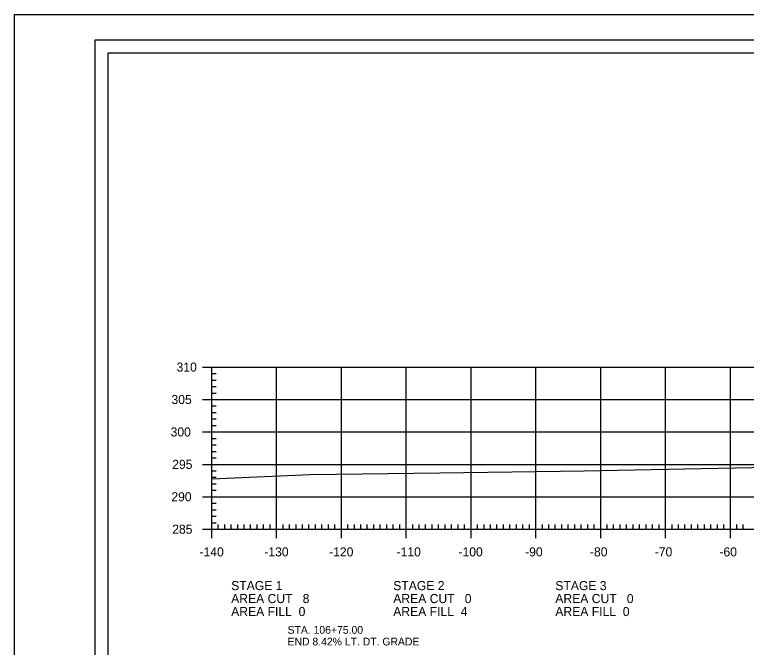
# Model space of a CAD drawing. Extents: x 1368713 to 1370673, y 380279 to 380950.
# Drawn here: x 1369981.9 to 1370094.8, y 380639.5 to 380737.1 of the extents above; entities that cross this region are included whole.
import ezdxf

# ---------------------------------------------------------------- set-up
doc = ezdxf.new("R2010")
doc.units = 0
for name, color, linetype in [('Notes', 7, 'Continuous'), ('R_Axis', 7, 'Continuous'), ('R_Axis Annot', 7, 'Continuous'), ('R_Border', 7, 'Continuous'), ('R_Exist Surface', 7, 'Continuous'), ('R_Grid', 7, 'Continuous'), ('R_No Plot', 7, 'Continuous')]:
    doc.layers.add(name, color=color, linetype=linetype)

msp = doc.modelspace()

# ---------------------------------------------------------------- linework, layer by layer
at = {"layer": 'R_Axis'}
for p, q in [((1370010.88, 380682.75), (1370013.68, 380682.75)), ((1370012.28, 380657.75), (1370012.28, 380682.75)), ((1370012.28, 380681.75), (1370012.98, 380681.75)), ((1370012.28, 380680.75), (1370012.98, 380680.75)), ((1370012.28, 380679.75), (1370012.98, 380679.75)), ((1370010.88, 380677.75), (1370013.68, 380677.75)), ((1370012.28, 380678.75), (1370012.98, 380678.75)), ((1370012.28, 380676.75), (1370012.98, 380676.75)), ((1370012.28, 380675.75), (1370012.98, 380675.75)), ((1370012.28, 380674.75), (1370012.98, 380674.75)), ((1370012.28, 380673.75), (1370012.98, 380673.75)), ((1370010.88, 380672.75), (1370013.68, 380672.75)), ((1370012.28, 380671.75), (1370012.98, 380671.75)), ((1370012.28, 380670.75), (1370012.98, 380670.75)), ((1370012.28, 380669.75), (1370012.98, 380669.75)), ((1370012.28, 380668.75), (1370012.98, 380668.75)), ((1370010.88, 380667.75), (1370013.68, 380667.75)), ((1370012.28, 380666.75), (1370012.98, 380666.75)), ((1370012.28, 380665.75), (1370012.98, 380665.75)), ((1370012.28, 380664.75), (1370012.98, 380664.75)), ((1370012.28, 380663.75), (1370012.98, 380663.75)), ((1370010.88, 380662.75), (1370013.68, 380662.75)), ((1370012.28, 380661.75), (1370012.98, 380661.75)), ((1370012.28, 380660.75), (1370012.98, 380660.75)), ((1370012.28, 380659.75), (1370012.98, 380659.75)), ((1370012.28, 380656.35), (1370012.28, 380659.15)), ((1370012.28, 380658.75), (1370012.98, 380658.75)), ((1370022.28, 380656.35), (1370022.28, 380659.15)), ((1370032.28, 380656.35), (1370032.28, 380659.15)), ((1370042.28, 380656.35), (1370042.28, 380659.15)), ((1370052.28, 380656.35), (1370052.28, 380659.15)), ((1370062.28, 380656.35), (1370062.28, 380659.15)), ((1370072.28, 380656.35), (1370072.28, 380659.15)), ((1370082.28, 380656.35), (1370082.28, 380659.15)), ((1370092.28, 380656.35), (1370092.28, 380659.15)), ((1370010.88, 380657.75), (1370013.68, 380657.75)), ((1370012.28, 380657.75), (1370292.28, 380657.75)), ((1370013.28, 380657.75), (1370013.28, 380658.45)), ((1370014.28, 380657.75), (1370014.28, 380658.45)), ((1370015.28, 380657.75), (1370015.28, 380658.45)), ((1370016.28, 380657.75), (1370016.28, 380658.45)), ((1370017.28, 380657.75), (1370017.28, 380658.45)), ((1370018.28, 380657.75), (1370018.28, 380658.45)), ((1370019.28, 380657.75), (1370019.28, 380658.45)), ((1370020.28, 380657.75), (1370020.28, 380658.45)), ((1370021.28, 380657.75), (1370021.28, 380658.45)), ((1370023.28, 380657.75), (1370023.28, 380658.45)), ((1370024.28, 380657.75), (1370024.28, 380658.45)), ((1370025.28, 380657.75), (1370025.28, 380658.45)), ((1370026.28, 380657.75), (1370026.28, 380658.45)), ((1370027.28, 380657.75), (1370027.28, 380658.45)), ((1370028.28, 380657.75), (1370028.28, 380658.45)), ((1370029.28, 380657.75), (1370029.28, 380658.45)), ((1370030.28, 380657.75), (1370030.28, 380658.45)), ((1370031.28, 380657.75), (1370031.28, 380658.45)), ((1370033.28, 380657.75), (1370033.28, 380658.45)), ((1370034.28, 380657.75), (1370034.28, 380658.45)), ((1370035.28, 380657.75), (1370035.28, 380658.45)), ((1370036.28, 380657.75), (1370036.28, 380658.45)), ((1370037.28, 380657.75), (1370037.28, 380658.45)), ((1370038.28, 380657.75), (1370038.28, 380658.45)), ((1370039.28, 380657.75), (1370039.28, 380658.45)), ((1370040.28, 380657.75), (1370040.28, 380658.45)), ((1370041.28, 380657.75), (1370041.28, 380658.45)), ((1370043.28, 380657.75), (1370043.28, 380658.45)), ((1370044.28, 380657.75), (1370044.28, 380658.45)), ((1370045.28, 380657.75), (1370045.28, 380658.45)), ((1370046.28, 380657.75), (1370046.28, 380658.45)), ((1370047.28, 380657.75), (1370047.28, 380658.45)), ((1370048.28, 380657.75), (1370048.28, 380658.45)), ((1370049.28, 380657.75), (1370049.28, 380658.45)), ((1370050.28, 380657.75), (1370050.28, 380658.45)), ((1370051.28, 380657.75), (1370051.28, 380658.45)), ((1370053.28, 380657.75), (1370053.28, 380658.45)), ((1370054.28, 380657.75), (1370054.28, 380658.45)), ((1370055.28, 380657.75), (1370055.28, 380658.45)), ((1370056.28, 380657.75), (1370056.28, 380658.45)), ((1370057.28, 380657.75), (1370057.28, 380658.45)), ((1370058.28, 380657.75), (1370058.28, 380658.45)), ((1370059.28, 380657.75), (1370059.28, 380658.45)), ((1370060.28, 380657.75), (1370060.28, 380658.45)), ((1370061.28, 380657.75), (1370061.28, 380658.45)), ((1370063.28, 380657.75), (1370063.28, 380658.45)), ((1370064.28, 380657.75), (1370064.28, 380658.45)), ((1370065.28, 380657.75), (1370065.28, 380658.45)), ((1370066.28, 380657.75), (1370066.28, 380658.45)), ((1370067.28, 380657.75), (1370067.28, 380658.45)), ((1370068.28, 380657.75), (1370068.28, 380658.45)), ((1370069.28, 380657.75), (1370069.28, 380658.45)), ((1370070.28, 380657.75), (1370070.28, 380658.45)), ((1370071.28, 380657.75), (1370071.28, 380658.45)), ((1370073.28, 380657.75), (1370073.28, 380658.45)), ((1370074.28, 380657.75), (1370074.28, 380658.45)), ((1370075.28, 380657.75), (1370075.28, 380658.45)), ((1370076.28, 380657.75), (1370076.28, 380658.45)), ((1370077.28, 380657.75), (1370077.28, 380658.45)), ((1370078.28, 380657.75), (1370078.28, 380658.45)), ((1370079.28, 380657.75), (1370079.28, 380658.45)), ((1370080.28, 380657.75), (1370080.28, 380658.45)), ((1370081.28, 380657.75), (1370081.28, 380658.45)), ((1370083.28, 380657.75), (1370083.28, 380658.45)), ((1370084.28, 380657.75), (1370084.28, 380658.45)), ((1370085.28, 380657.75), (1370085.28, 380658.45)), ((1370086.28, 380657.75), (1370086.28, 380658.45)), ((1370087.28, 380657.75), (1370087.28, 380658.45)), ((1370088.28, 380657.75), (1370088.28, 380658.45)), ((1370089.28, 380657.75), (1370089.28, 380658.45)), ((1370090.28, 380657.75), (1370090.28, 380658.45)), ((1370091.28, 380657.75), (1370091.28, 380658.45)), ((1370093.28, 380657.75), (1370093.28, 380658.45)), ((1370094.28, 380657.75), (1370094.28, 380658.45))]:
    msp.add_line(p, q, dxfattribs=at)
at = {"layer": 'R_Border'}
for p, q in [((1369994.28, 380733.21), (1370310.46, 380733.21)), ((1369994.28, 380527.75), (1369994.28, 380733.21))]:
    msp.add_line(p, q, dxfattribs=at)
at = {"layer": 'R_Exist Surface'}
msp.add_lwpolyline([(1370012.28, 380665.5), (1370027.47, 380666.16), (1370047.49, 380666.44), (1370069.74, 380666.74), (1370100.77, 380667.35)], dxfattribs=at)
at = {"layer": 'R_Grid'}
for p, q in [((1370012.28, 380682.75), (1370292.28, 380682.75)), ((1370012.28, 380657.75), (1370012.28, 380682.75)), ((1370022.28, 380657.75), (1370022.28, 380682.75)), ((1370032.28, 380657.75), (1370032.28, 380682.75)), ((1370042.28, 380657.75), (1370042.28, 380682.75)), ((1370052.28, 380657.75), (1370052.28, 380682.75)), ((1370062.28, 380657.75), (1370062.28, 380682.75)), ((1370072.28, 380657.75), (1370072.28, 380682.75)), ((1370082.28, 380657.75), (1370082.28, 380682.75)), ((1370092.28, 380657.75), (1370092.28, 380682.75)), ((1370012.28, 380677.75), (1370292.28, 380677.75)), ((1370012.28, 380672.75), (1370292.28, 380672.75)), ((1370012.28, 380667.75), (1370292.28, 380667.75)), ((1370012.28, 380662.75), (1370292.28, 380662.75)), ((1370012.28, 380657.75), (1370292.28, 380657.75))]:
    msp.add_line(p, q, dxfattribs=at)
at = {"layer": 'R_No Plot'}
for points in [[(1369981.88, 380737.11), (1370315.22, 380737.11), (1370315.22, 380523.77), (1369981.88, 380523.77)], [(1370308.46, 380632.48), (1369996.28, 380632.48), (1369996.28, 380731.21), (1370245.82, 380731.21), (1370245.82, 380721.33), (1370263.36, 380721.33), (1370287.46, 380721.33), (1370287.46, 380699), (1370308.46, 380699)], [(1369996.28, 380731.21), (1370245.82, 380731.21), (1370245.82, 380721.33), (1370263.36, 380721.33), (1370287.46, 380721.33), (1370287.46, 380699), (1370308.46, 380699), (1370308.46, 380529.75), (1369996.28, 380529.75)]]:
    msp.add_lwpolyline(points, close=True, dxfattribs=at)

# ---------------------------------------------------------------- texts
at = {"layer": 'Notes'}
for s, p in [('STA. 106+75.00', (1370023.98, 380641.62)), ('END 8.42% LT. DT. GRADE', (1370023.98, 380639.82))]:
    msp.add_text(s, height=1.2, dxfattribs=at).set_placement(p)
at = {"layer": 'R_Axis Annot'}
for s, p in [('310', (1370006.85, 380682.05)), ('305', (1370006.07, 380677.05)), ('300', (1370005.94, 380672.05)), ('295', (1370006.18, 380667.05)), ('290', (1370006.05, 380662.05)), ('285', (1370006.18, 380657.05)), ('-140', (1370010.39, 380653.55)), ('-130', (1370020.39, 380653.55)), ('-120', (1370030.39, 380653.55)), ('-110', (1370040.79, 380653.55)), ('-100', (1370050.34, 380653.55)), ('-90', (1370060.62, 380653.55)), ('-80', (1370070.62, 380653.55)), ('-70', (1370080.62, 380653.55)), ('-60', (1370090.59, 380653.55)), ('STAGE 1', (1370015.28, 380648.35)), ('STAGE 2', (1370040.28, 380648.35)), ('STAGE 3', (1370065.28, 380648.35)), ('AREA CUT   8', (1370015.28, 380646.35)), ('AREA CUT   0', (1370040.28, 380646.35)), ('AREA CUT   0', (1370065.28, 380646.35)), ('AREA FILL  0', (1370015.28, 380644.35)), ('AREA FILL  4', (1370040.28, 380644.35)), ('AREA FILL  0', (1370065.28, 380644.35))]:
    msp.add_text(s, height=1.4, dxfattribs=at).set_placement(p)

doc.saveas('drawing.dxf')
